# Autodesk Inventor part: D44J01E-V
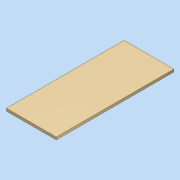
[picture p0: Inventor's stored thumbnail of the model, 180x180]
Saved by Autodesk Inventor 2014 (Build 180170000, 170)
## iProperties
Created: 2011-04
Part Number: D44J01E-V
Document SubType Name: Modeling
Designer: david.appleford
Density: 0.342536 g/cm^3
Description: 836 x 1981 Plain External Door
Mass: 25000 g
Surface Area: 35693.7 cm^2
Volume: 72985.1 cm^3
Cost Center: £216.00
Material: 000 Redwood
Appearance: Wheat
Justset: False
Author: david.appleford
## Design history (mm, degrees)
sketch "Sketch1"
  geometry: L1 (0, 0)-(838, 0); L2 (838, 0)-(838, 1981); L3 (838, 1981)-(0, 1981); L4 (0, 1981)-(0, 0)
  constraints: 8 end point, 2 parallel, 1 horizontal, 1 perpendicular
  dimensions: "d0" = 1981 distance between parallel lines of L1 L3; "d1" = 838 distance between parallel lines of L2 L4
extrude "Extrusion1" new body sketch "Sketch1" distance "d2" = 44; taper "d3" = 0 deg
sketch "Sketch2"
  geometry: L1 (0, 299)-(37, 299); L2 (37, 299)-(37, 197); L3 (37, 197)-(0, 197); L4 (0, 197)-(0, 299); L5 (0, 0)-(44, 0) reference; L6 (0, 1784)-(37, 1784); L7 (37, 1784)-(37, 1682); L8 (37, 1682)-(0, 1682); L9 (0, 1682)-(0, 1784); L10 (0, 1981)-(0, 0) reference; L11 (37, 248)-(105.977, 248); L12 (0, 1981)-(44, 1981) reference; L13 (0, 1041.5)-(37, 1041.5); L14 (37, 1041.5)-(37, 939.5); L15 (37, 939.5)-(0, 939.5); L16 (0, 939.5)-(0, 1041.5); L17 (37, 1733)-(105.977, 1733); L18 (37, 990.5)-(80.437, 990.5); L19 (-27.903, 288.229)-(-27.903, 186.229) reference
  constraints: 30 end point, 7 parallel, 5 perpendicular, 4 collinear, 3 horizontal, 3 midpoint, 1 point on line
  dimensions: "d6" = 197 distance between parallel lines of L3 L5; "d8" = 102 distance between parallel lines of L3 L1 (= d9); "d9" = 102 distance between parallel lines of L8 L6; "d13" = 197 distance between parallel lines of L6 L12; "d14" = 37 distance between parallel lines of L2 L4; "d15" = 102 distance between parallel lines of L15 L13; "d16" = 1485 distance between parallel lines of L11 L17 (derived); "d17" = 742.5 distance between parallel lines of L18 L17 (= 0.5 x d16)
  node "Reference2"
workplane "Work Plane1"
workplane "Work Plane2"
extrude "Extrusion2" cut sketch "Sketch2" stored distance "d4" = 10; taper "d5" = 0 deg
body "Solid1"
other parameters: "d7" = 72.77382 (derived)
